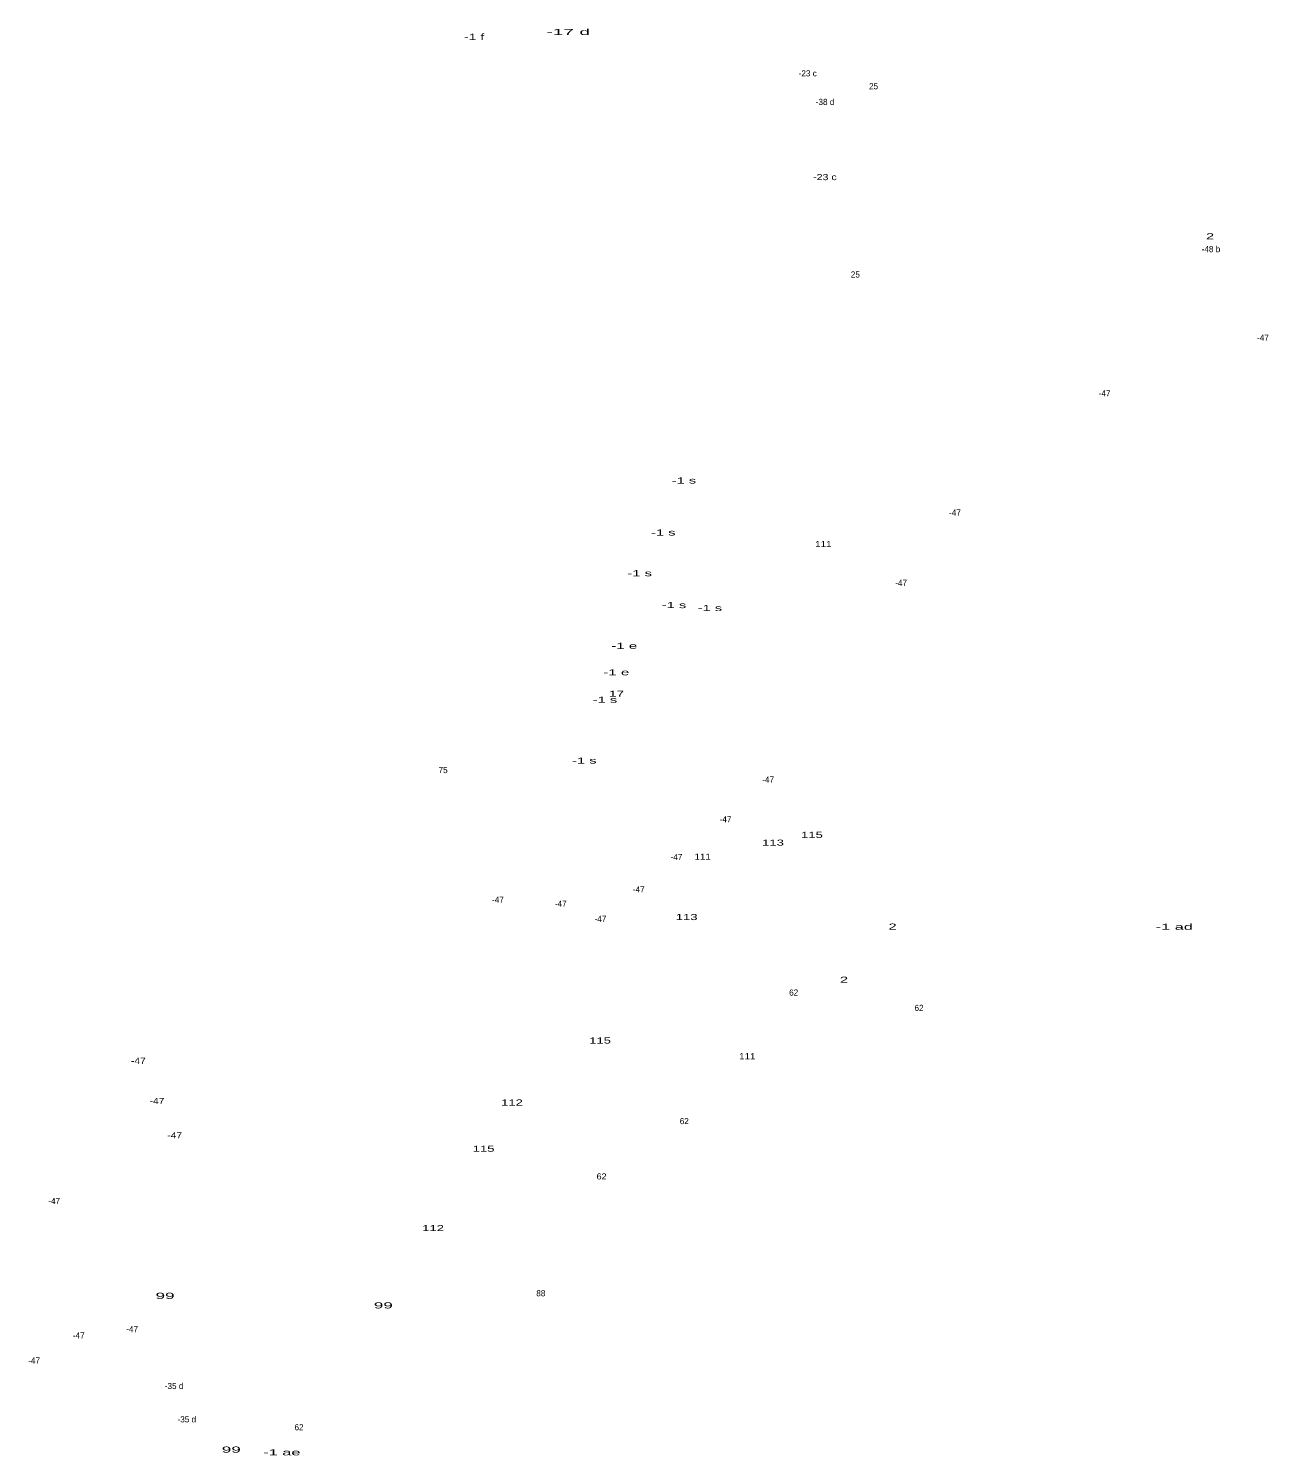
# Model space of a CAD drawing. Extents: x -668622 to -666786, y -990362 to -986505.
# Drawn here: x -668622 to -667810, y -989374 to -988439 of the extents above; entities that cross this region are included whole.
import ezdxf
from ezdxf.enums import TextEntityAlignment as Align

# ---------------------------------------------------------------- set-up
doc = ezdxf.new("R2010")
doc.units = 0
doc.header["$LTSCALE"] = 1.6
doc.layers.add('24', color=7, linetype='Continuous')

msp = doc.modelspace()

# ---------------------------------------------------------------- texts
at = {"layer": '24'}
for s, width, p in [('-1 f', 1.7, (-668330.493, -988446.33)), ('-17 d', 2.35, (-668268.865, -988443.14)), ('-23 c', 1.3, (-668100.679, -988538.24)), ('2', 1.8, (-667848.351, -988577.01)), ('-1 s', 1.8, (-668193.086, -988737.03)), ('-1 s', 1.8, (-668206.586, -988771.1)), ('111', 1.2, (-668101.72, -988778.7)), ('-1 s', 1.8, (-668222.006, -988797.77)), ('-1 s', 1.8, (-668199.516, -988818.66)), ('-1 s', 1.8, (-668176.066, -988820.58)), ('-1 e', 1.85, (-668232.191, -988845.33)), ('-1 e', 1.85, (-668237.331, -988862.68)), ('-1 s', 1.8, (-668244.816, -988880.68)), ('17', 1.65, (-668237.193, -988876.73)), ('-1 s', 1.8, (-668258.306, -988920.53)), ('113', 1.6, (-668134.684, -988974.29)), ('115', 1.6, (-668109.184, -988969.19)), ('111', 1.2, (-668180.75, -988983.5)), ('113', 1.6, (-668191.254, -989023.04)), ('2', 1.8, (-668056.381, -989029.31)), ('-1 ad', 2, (-667871.787, -989029.41)), ('2', 1.8, (-668088.171, -989064.1)), ('115', 1.6, (-668247.984, -989103.93)), ('111', 1.2, (-668151.52, -989114.2)), ('-47', 1.25, (-668550.481, -989117.23)), ('-47', 1.25, (-668538.27, -989143.59)), ('112', 1.6, (-668305.694, -989144.56)), ('-47', 1.25, (-668526.701, -989166.08)), ('115', 1.6, (-668324.314, -989174.85)), ('62', 1.1, (-668246.99, -989192.97)), ('112', 1.6, (-668357.394, -989226.84)), ('99', 2.1, (-668533.011, -989271.19)), ('99', 2.1, (-668389.991, -989277.48)), ('99', 2.1, (-668489.601, -989371.95)), ('-1 ae', 2, (-668456.487, -989373.74))]:
    msp.add_text(s, height=4, dxfattribs=dict(at, width=width)).set_placement(p, align=Align.CENTER)
for s, p in [('-23 c', (-668111.932, -988470.28)), ('25', (-668068.787, -988478.7)), ('-38 d', (-668100.583, -988488.98)), ('-48 b', (-667847.747, -988585.45)), ('25', (-668080.747, -988602.08)), ('-47', (-667813.675, -988643.45)), ('-47', (-667917.465, -988679.92)), ('-47', (-668015.455, -988758.01)), ('-47', (-668050.785, -988804.1)), ('75', (-668350.833, -988926.74)), ('-47', (-668137.855, -988932.96)), ('-47', (-668165.805, -988958.99)), ('-47', (-668197.935, -988983.74)), ('-47', (-668314.875, -989011.7)), ('-47', (-668222.675, -989004.95)), ('-47', (-668273.755, -989014.27)), ('-47', (-668247.735, -989024.23)), ('62', (-668121.153, -989072.52)), ('62', (-668039.013, -989082.57)), ('62', (-668192.823, -989156.73)), ('-47', (-668605.635, -989209.14)), ('88', (-668286.807, -989269.5)), ('-47', (-668589.565, -989297.19)), ('-47', (-668554.545, -989293.02)), ('-47', (-668618.805, -989313.58)), ('-35 d', (-668527.083, -989330.29)), ('-35 d', (-668518.723, -989352.14)), ('62', (-668445.233, -989357.32))]:
    msp.add_text(s, height=4, dxfattribs=at).set_placement(p, align=Align.CENTER)

doc.saveas('drawing.dxf')
